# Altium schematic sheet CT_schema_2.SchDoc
size 322 x 229 mm
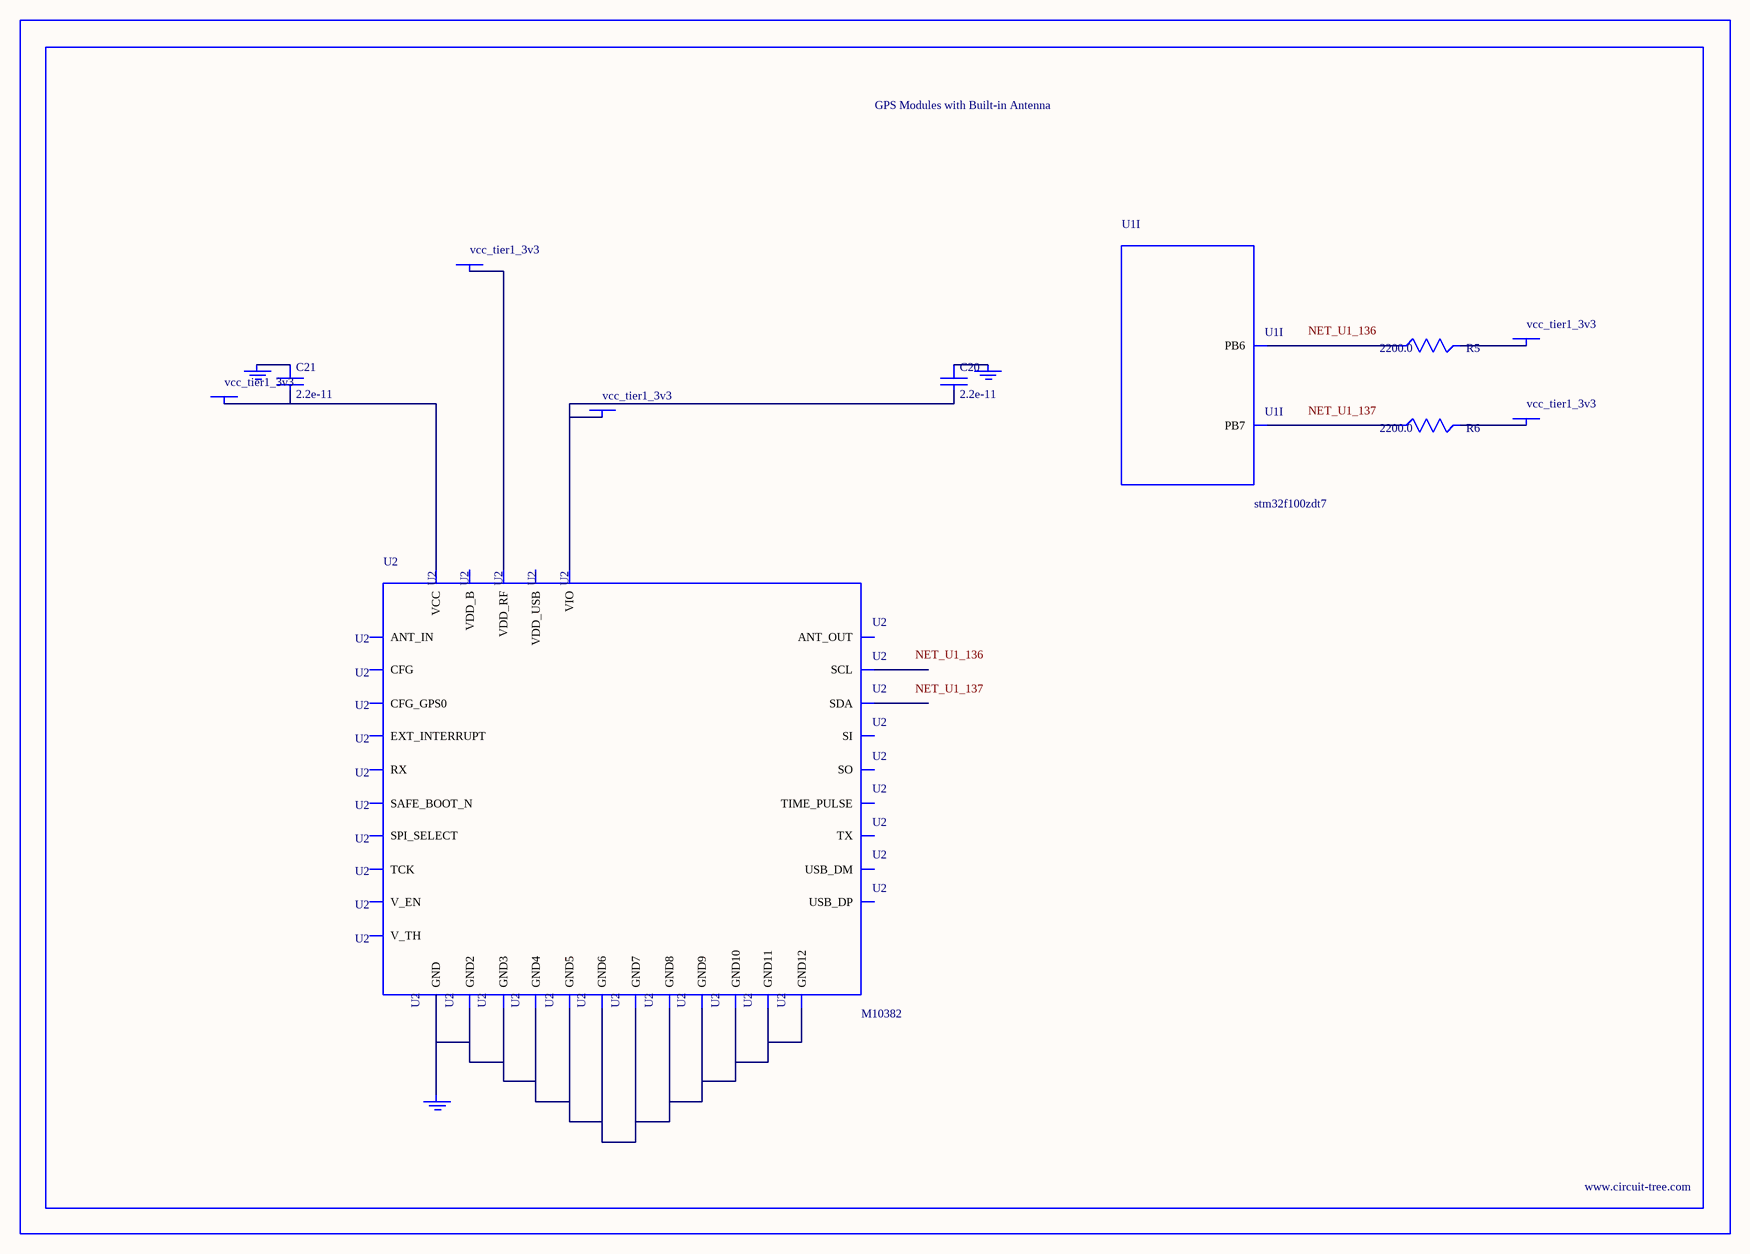
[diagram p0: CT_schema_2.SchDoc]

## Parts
BORDER1  (no value)
C20  2.2e-11  [C0402]
C21  2.2e-11  [C0402]
GND_INSTANCE_1_0  (no value)
GND_INSTANCE_1_1  (no value)
GND_INSTANCE_1_2  (no value)
POWER_INSTANCE_1_0  vcc_tier1_3v3
POWER_INSTANCE_1_1  vcc_tier1_3v3
POWER_INSTANCE_1_2  vcc_tier1_3v3
POWER_INSTANCE_1_3  vcc_tier1_3v3
POWER_INSTANCE_1_4  vcc_tier1_3v3
R5  2200.0  [R0603]
R6  2200.0  [R0603]
U1  stm32f100zdt7  [LQFP144]  (part I of 12)
U2  M10382  [M10382]

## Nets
NetC20_1: C20.1 GND_INSTANCE_1_0.0(GND)
NetC20_2: C20.2 POWER_INSTANCE_1_0.0(PWR) U2.5(VIO)
NetC21_1: C21.1 GND_INSTANCE_1_1.0(GND)
NetC21_2: C21.2 POWER_INSTANCE_1_2.0(PWR) U2.27(VCC)
NetGND_INSTANCE_1_2_0: GND_INSTANCE_1_2.0(GND) U2.2(GND) U2.4(GND2) U2.14(GND3) U2.17(GND4) U2.21(GND5) U2.24(GND6) U2.26(GND7) U2.28(GND8) U2.33(GND9) U2.34(GND10) U2.35(GND11) U2.36(GND12)
NetPOWER_INSTANCE_1_1_0: POWER_INSTANCE_1_1.0(PWR) U2.25(VDD_RF)
NetPOWER_INSTANCE_1_3_0: POWER_INSTANCE_1_3.0(PWR) R5.2
NetPOWER_INSTANCE_1_4_0: POWER_INSTANCE_1_4.0(PWR) R6.2
NetR5_1: R5.1 U1.136(PB6)
NetR6_1: R6.1 U1.137(PB7)

Not connected (* = marked no-connect by the designer): U2 1(ANT_IN) 3(ANT_OUT) 6(USB_DP) 7(USB_DM) 8(SO) 9(CFG_GPS0) 10(SPI_SELECT) 11(TX) 12(V_TH) 13(RX) 15(VDD_B) 16(SI) 18(SDA) 19(SCL) 20(SAFE_BOOT_N) 22(TCK) 23(TIME_PULSE) 29(EXT_INTERRUPT) 30(V_EN) 31(CFG) 32(VDD_USB)

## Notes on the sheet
- Labels drawn without touching a wire or pin: NET_U1_136, NET_U1_137

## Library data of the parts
BORDER1 = BORDER_PAGE1
C20 C21 = C0402C220K3RAC
GND_INSTANCE_1_0-GND_INSTANCE_1_2 = GND
POWER_INSTANCE_1_0-POWER_INSTANCE_1_4 = PWR
R5 R6 = RC0603JR-072K2L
